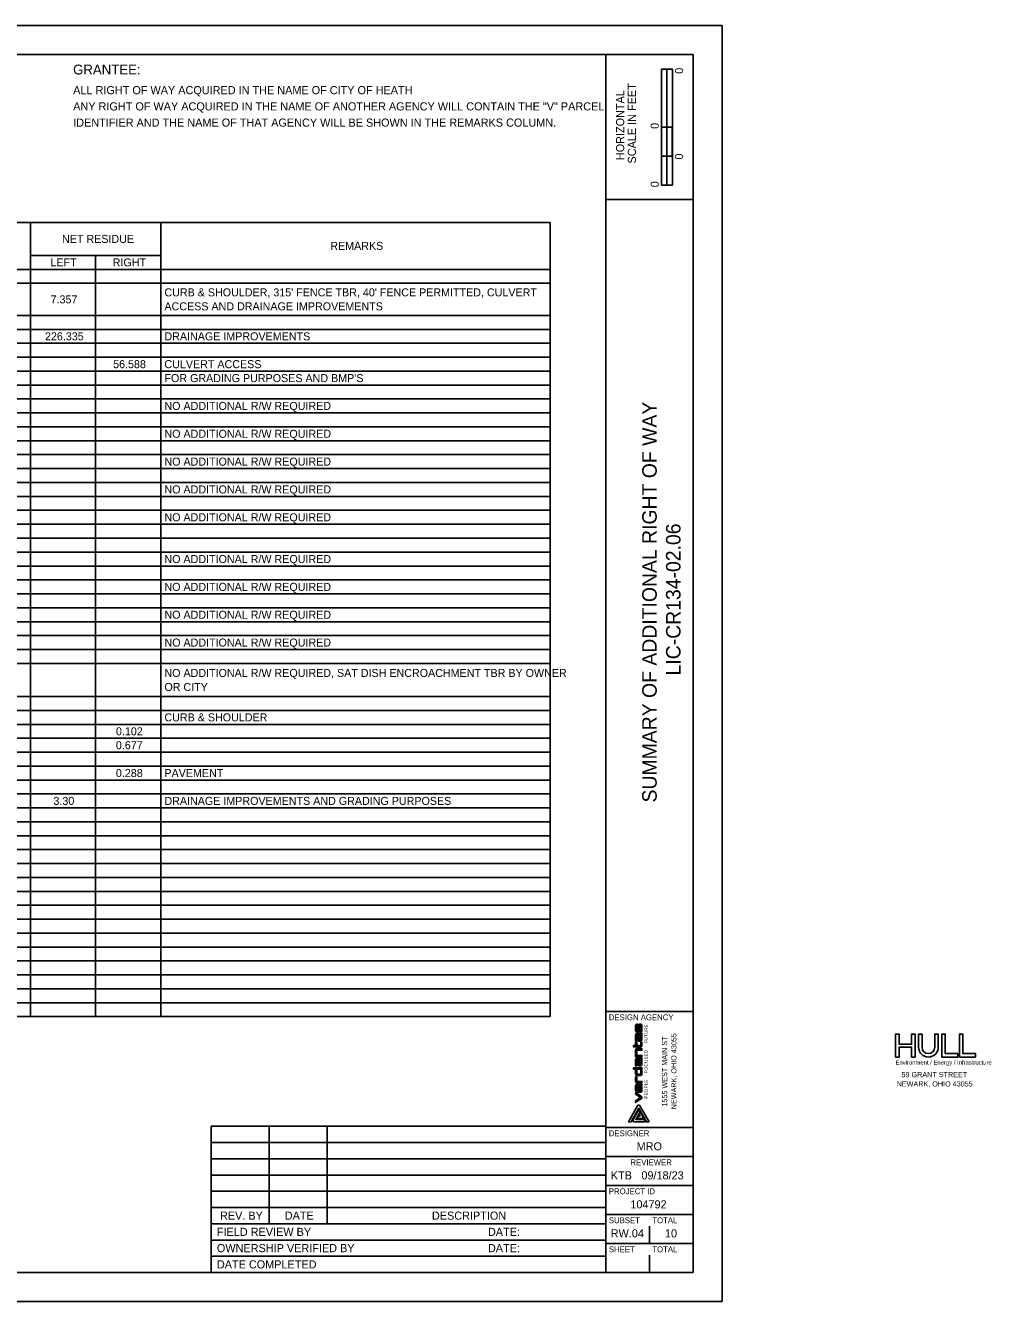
# Model space of a CAD drawing. Extents: x 0 to 38.6, y 0 to 22.
# Drawn here: x 22 to 38.59, y 0 to 22 of the extents above; entities that cross this region are included whole.
import ezdxf

# ---------------------------------------------------------------- set-up
doc = ezdxf.new("R2010")
doc.units = 0
for name, color, linetype in [('CS-ANNO-TTLB-LOGO', 7, 'Continuous'), ('Default', 7, 'Continuous'), ('SH_Border', 7, 'Continuous'), ('SH_Cut_Line', 7, 'Continuous'), ('SH_Data', 7, 'Continuous'), ('SH_Text', 7, 'Continuous')]:
    doc.layers.add(name, color=color, linetype=linetype)

msp = doc.modelspace()

# ---------------------------------------------------------------- linework, layer by layer
at = {"layer": 'CS-ANNO-TTLB-LOGO'}
for p, q in [((32.512, 4.761), (32.512, 4.668)), ((32.543, 4.783), (32.535, 4.783)), ((32.535, 4.645), (32.551, 4.645)), ((32.596, 4.783), (32.58, 4.783)), ((32.619, 4.668), (32.619, 4.761)), ((32.512, 4.488), (32.512, 4.6)), ((32.512, 4.063), (32.512, 4.175)), ((32.535, 3.894), (32.596, 3.894)), ((32.619, 3.633), (32.619, 3.745)), ((32.512, 3.723), (32.512, 3.633)), ((32.535, 3.61), (32.596, 3.61))]:
    msp.add_line(p, q, dxfattribs=at)
for points in [[(32.557, 4.761), (32.557, 4.673), (32.532, 4.673), (32.532, 4.761), (32.543, 4.761), (32.543, 4.783)], [(32.535, 4.623), (32.619, 4.623), (32.619, 4.51)], [(32.574, 4.668), (32.574, 4.761), (32.599, 4.761), (32.599, 4.673), (32.591, 4.673), (32.591, 4.645), (32.596, 4.645)], [(32.477, 4.412), (32.512, 4.412), (32.512, 4.468), (32.532, 4.468), (32.532, 4.412), (32.599, 4.412), (32.599, 4.468), (32.619, 4.468), (32.619, 4.412)], [(32.596, 4.389), (32.477, 4.389), (32.477, 4.412)], [(32.596, 4.488), (32.557, 4.488), (32.557, 4.6), (32.532, 4.6), (32.532, 4.488), (32.512, 4.488)], [(32.512, 4.339), (32.512, 4.22), (32.619, 4.22), (32.619, 4.243), (32.532, 4.243), (32.532, 4.333), (32.619, 4.333)], [(32.619, 4.333), (32.619, 4.361), (32.535, 4.361)], [(32.535, 4.198), (32.619, 4.198), (32.619, 4.085)], [(32.477, 4.029), (32.477, 4.007), (32.512, 4.007), (32.512, 3.917)], [(32.619, 3.917), (32.619, 4.029), (32.477, 4.029)], [(32.596, 4.063), (32.557, 4.063), (32.557, 4.175), (32.532, 4.175), (32.532, 4.063), (32.512, 4.063)], [(32.619, 3.793), (32.532, 3.793), (32.532, 3.872), (32.512, 3.872), (32.512, 3.793)], [(32.535, 3.77), (32.619, 3.77), (32.619, 3.793)], [(32.619, 3.745), (32.599, 3.745), (32.599, 3.633), (32.574, 3.633), (32.574, 3.745), (32.535, 3.745)]]:
    msp.add_lwpolyline(points, dxfattribs=at)
for points in [[(32.574, 4.6), (32.599, 4.6), (32.599, 4.51), (32.574, 4.51)], [(32.532, 4.007), (32.532, 3.917), (32.599, 3.917), (32.599, 4.007)], [(32.574, 4.175), (32.599, 4.175), (32.599, 4.085), (32.574, 4.085)], [(32.597, 3.516), (32.512, 3.457), (32.512, 3.43), (32.619, 3.505), (32.619, 3.528), (32.513, 3.603), (32.512, 3.575)], [(32.557, 3.723), (32.532, 3.723), (32.532, 3.633), (32.557, 3.633)]]:
    msp.add_lwpolyline(points, close=True, dxfattribs=at)
for centre, start, end in [((32.535, 4.761), 90, 180), ((32.535, 4.668), 180, 270), ((32.535, 4.6), 90, 180), ((32.551, 4.668), 270, 0), ((32.58, 4.761), 90, 180), ((32.596, 4.761), 360, 90), ((32.596, 4.668), 270, 0), ((32.596, 4.51), 270, 360), ((32.596, 4.412), 270, 360), ((32.535, 4.339), 90, 180), ((32.535, 4.175), 90, 180), ((32.596, 4.085), 270, 360), ((32.535, 3.917), 180, 270), ((32.535, 3.793), 180, 270), ((32.535, 3.723), 90, 180), ((32.596, 3.917), 270, 0), ((32.535, 3.633), 180, 270), ((32.596, 3.633), 270, 0)]:
    msp.add_arc(centre, 0.0225, start, end, dxfattribs=at)
at = {"layer": 'Default'}
for p, q in [((32.512, 4.761), (32.512, 4.668)), ((32.535, 4.645), (32.551, 4.645)), ((32.596, 4.783), (32.58, 4.783)), ((32.619, 4.668), (32.619, 4.761)), ((37.556, 4.275), (37.556, 4.275)), ((37.556, 4.275), (37.556, 4.275)), ((37.556, 4.215), (37.556, 4.215)), ((32.535, 3.894), (32.596, 3.894)), ((32.512, 3.723), (32.512, 3.633)), ((32.535, 3.61), (32.596, 3.61)), ((32.462, 3.126), (32.565, 3.309)), ((32.565, 3.309), (32.588, 3.269)), ((32.477, 3.098), (32.462, 3.126)), ((32.684, 3.098), (32.477, 3.098)), ((32.588, 3.269), (32.513, 3.138)), ((32.513, 3.138), (32.662, 3.138)), ((32.662, 3.138), (32.684, 3.098))]:
    msp.add_line(p, q, dxfattribs=at)
for points in [[(32.557, 4.761), (32.557, 4.673), (32.532, 4.673), (32.532, 4.761), (32.543, 4.761), (32.543, 4.783), (32.535, 4.783)], [(32.619, 4.51), (32.619, 4.623), (32.535, 4.623)], [(32.574, 4.668), (32.574, 4.761), (32.599, 4.761), (32.599, 4.673), (32.591, 4.673), (32.591, 4.645), (32.596, 4.645)], [(32.619, 4.412), (32.619, 4.468), (32.599, 4.468), (32.599, 4.412), (32.532, 4.412), (32.532, 4.468), (32.512, 4.468), (32.512, 4.412), (32.477, 4.412), (32.477, 4.389), (32.596, 4.389)], [(32.512, 4.6), (32.512, 4.488), (32.532, 4.488), (32.532, 4.6), (32.557, 4.6), (32.557, 4.488), (32.596, 4.488)], [(37.327, 4.611), (37.327, 4.611), (37.327, 4.215), (37.266, 4.215), (37.266, 4.383), (37.051, 4.383), (37.051, 4.215), (36.991, 4.215), (36.991, 4.611), (37.051, 4.611), (37.051, 4.436), (37.266, 4.436), (37.266, 4.611), (37.327, 4.611)], [(37.447, 4.383), (37.447, 4.611), (37.387, 4.611), (37.387, 4.383)], [(37.387, 4.383), (37.387, 4.611), (37.447, 4.611), (37.447, 4.383)], [(37.725, 4.383), (37.725, 4.611), (37.664, 4.611), (37.664, 4.383)], [(37.664, 4.383), (37.664, 4.611), (37.725, 4.611), (37.725, 4.383)], [(32.512, 4.339), (32.512, 4.22), (32.619, 4.22), (32.619, 4.243), (32.532, 4.243), (32.532, 4.333), (32.619, 4.333), (32.619, 4.361), (32.535, 4.361)], [(32.619, 4.085), (32.619, 4.198), (32.535, 4.198)], [(32.619, 3.917), (32.619, 4.029), (32.477, 4.029), (32.477, 4.007), (32.512, 4.007), (32.512, 3.917)], [(32.512, 4.175), (32.512, 4.063), (32.532, 4.063), (32.532, 4.175), (32.557, 4.175), (32.557, 4.063), (32.596, 4.063)], [(32.535, 3.77), (32.619, 3.77), (32.619, 3.793), (32.532, 3.793), (32.532, 3.872), (32.512, 3.872), (32.512, 3.793)], [(32.619, 3.633), (32.619, 3.745), (32.599, 3.745), (32.599, 3.633), (32.574, 3.633), (32.574, 3.745), (32.535, 3.745)]]:
    msp.add_lwpolyline(points, dxfattribs=at)
for points in [[(32.599, 4.6), (32.599, 4.51), (32.574, 4.51), (32.574, 4.6)], [(37.327, 4.611), (37.266, 4.611), (37.266, 4.436), (37.051, 4.436), (37.051, 4.611), (36.991, 4.611), (36.991, 4.215), (37.051, 4.215), (37.051, 4.383), (37.266, 4.383), (37.266, 4.215), (37.327, 4.215)], [(37.845, 4.611), (37.785, 4.611), (37.785, 4.215), (38.061, 4.215), (38.061, 4.275), (37.845, 4.275)], [(37.785, 4.611), (37.785, 4.215), (38.061, 4.215), (38.061, 4.275), (37.845, 4.275), (37.845, 4.611)], [(38.15, 4.611), (38.09, 4.611), (38.09, 4.215), (38.366, 4.215), (38.366, 4.275), (38.15, 4.275)], [(38.09, 4.611), (38.09, 4.215), (38.366, 4.215), (38.366, 4.275), (38.15, 4.275), (38.15, 4.611)], [(32.532, 4.007), (32.599, 4.007), (32.599, 3.917), (32.532, 3.917)], [(32.599, 4.175), (32.599, 4.085), (32.574, 4.085), (32.574, 4.175)], [(32.512, 3.457), (32.512, 3.43), (32.619, 3.505), (32.619, 3.528), (32.513, 3.603), (32.512, 3.575), (32.597, 3.516)], [(32.557, 3.723), (32.557, 3.633), (32.532, 3.633), (32.532, 3.723)], [(32.565, 3.332), (32.697, 3.098), (32.742, 3.098), (32.581, 3.384), (32.549, 3.384), (32.388, 3.098), (32.433, 3.098)], [(32.433, 3.098), (32.565, 3.332), (32.697, 3.098), (32.742, 3.098), (32.581, 3.384), (32.549, 3.384), (32.388, 3.098)], [(32.462, 3.126), (32.477, 3.098), (32.684, 3.098), (32.662, 3.138), (32.513, 3.138), (32.588, 3.269), (32.565, 3.309)], [(32.558, 3.194), (32.536, 3.155), (32.626, 3.155), (32.639, 3.178), (32.594, 3.258), (32.571, 3.218), (32.585, 3.194)], [(32.558, 3.194), (32.585, 3.194), (32.571, 3.218), (32.594, 3.258), (32.639, 3.178), (32.626, 3.155), (32.536, 3.155)]]:
    msp.add_lwpolyline(points, close=True, dxfattribs=at)
for centre, radius, start, end in [((32.535, 4.761), 0.0225, 90, 180), ((32.535, 4.668), 0.0225, 180, 270), ((32.535, 4.6), 0.0225, 90, 180), ((32.551, 4.668), 0.0225, 270, 0), ((32.58, 4.761), 0.0225, 90, 180), ((32.596, 4.761), 0.0225, 360, 90), ((32.596, 4.668), 0.0225, 270, 0), ((32.596, 4.51), 0.0225, 270, 0), ((32.596, 4.412), 0.0225, 270, 0), ((32.535, 4.339), 0.0225, 90, 180), ((32.535, 4.175), 0.0225, 90, 180), ((37.556, 4.383), 0.169, 180, 270.0443), ((37.556, 4.383), 0.169, 180, 270), ((37.556, 4.383), 0.108, 180, 270), ((37.556, 4.383), 0.108, 180, 270), ((37.556, 4.383), 0.108, 270, 0), ((37.556, 4.383), 0.169, 269.9557, 360), ((37.556, 4.383), 0.108, 270, 0), ((37.556, 4.383), 0.169, 270, 0), ((32.596, 4.085), 0.0225, 270, 0), ((32.535, 3.917), 0.0225, 180, 270), ((32.535, 3.793), 0.0225, 180, 270), ((32.535, 3.723), 0.0225, 90, 180), ((32.596, 3.917), 0.0225, 270, 0), ((32.535, 3.633), 0.0225, 180, 270), ((32.596, 3.633), 0.0225, 270, 0)]:
    msp.add_arc(centre, radius, start, end, dxfattribs=at)
at = {"layer": 'SH_Border'}
for p, q in [((32, 0.5), (32, 21.5)), ((32, 19), (33.5, 19)), ((32, 5), (33.5, 5)), ((32, 3), (33.5, 3)), ((32, 2.5), (33.5, 2.5)), ((32, 2), (33.5, 2)), ((32, 1.5), (33.5, 1.5)), ((32, 1), (33.5, 1))]:
    msp.add_line(p, q, dxfattribs=at)
msp.add_lwpolyline([(1.5, 21.5), (33.5, 21.5), (33.5, 0.5), (1.5, 0.5)], close=True, dxfattribs=at)
at = {"layer": 'SH_Cut_Line'}
msp.add_lwpolyline([(0, 0), (34, 0), (34, 22), (0, 22)], close=True, dxfattribs=at)
at = {"layer": 'SH_Data'}
for p, q in [((32.957, 19.25), (32.957, 21.25)), ((33.144, 21.25), (32.957, 21.25)), ((32.957, 20.25), (32.957, 21.25)), ((32.957, 21.25), (33.05, 21.25)), ((33.05, 21.25), (33.051, 21.25)), ((33.051, 21.25), (33.051, 20.25)), ((33.144, 21.25), (33.144, 19.25)), ((33.051, 20.25), (32.957, 20.25)), ((33.143, 20.25), (33.05, 20.25)), ((33.05, 20.25), (33.05, 19.75)), ((33.143, 19.75), (33.143, 20.25)), ((33.05, 19.75), (32.957, 19.75)), ((32.957, 19.75), (32.957, 19.25)), ((33.05, 19.75), (33.143, 19.75)), ((33.05, 19.25), (33.05, 19.75)), ((33.144, 19.25), (32.957, 19.25)), ((32.957, 19.25), (33.05, 19.25)), ((32.75, 4), (32.75, 4)), ((32.75, 1), (32.75, 1.3)), ((32.375, 0.675), (32.375, 0.675)), ((32.75, 0.5), (32.75, 0.8))]:
    msp.add_line(p, q, dxfattribs=at)
at = {"layer": 'SH_Text'}
for p, q in [((2.373, 18.606), (31.038, 18.606)), ((22.083, 18.606), (22.083, 4.911)), ((24.333, 18.606), (24.333, 4.911)), ((31.038, 18.606), (31.038, 4.911)), ((22.083, 18.036), (24.333, 18.036)), ((23.208, 18.036), (23.208, 4.911)), ((2.373, 17.796), (31.038, 17.796)), ((2.373, 17.556), (31.038, 17.556)), ((2.373, 17.001), (31.038, 17.001)), ((2.373, 16.761), (31.038, 16.761)), ((2.373, 16.521), (31.038, 16.521)), ((2.373, 16.281), (31.038, 16.281)), ((17.448, 16.041), (31.038, 16.041)), ((2.373, 15.801), (31.038, 15.801)), ((2.373, 15.561), (31.038, 15.561)), ((2.373, 15.321), (31.038, 15.321)), ((2.373, 15.081), (31.038, 15.081)), ((2.373, 14.841), (31.038, 14.841)), ((2.373, 14.601), (31.038, 14.601)), ((2.373, 14.361), (31.038, 14.361)), ((2.373, 14.121), (31.038, 14.121)), ((2.373, 13.881), (31.038, 13.881)), ((2.373, 13.641), (31.038, 13.641)), ((2.373, 13.401), (31.038, 13.401)), ((2.373, 13.161), (31.038, 13.161)), ((2.373, 12.921), (31.038, 12.921)), ((2.373, 12.681), (31.038, 12.681)), ((2.373, 12.441), (31.038, 12.441)), ((2.373, 12.201), (31.038, 12.201)), ((2.373, 11.961), (31.038, 11.961)), ((2.373, 11.721), (31.038, 11.721)), ((2.373, 11.481), (31.038, 11.481)), ((2.373, 11.241), (31.038, 11.241)), ((2.373, 11.001), (31.038, 11.001)), ((2.373, 10.431), (31.038, 10.431)), ((2.373, 10.191), (31.038, 10.191)), ((2.373, 9.951), (31.038, 9.951)), ((2.373, 9.711), (31.038, 9.711)), ((2.373, 9.471), (31.038, 9.471)), ((2.373, 9.231), (31.038, 9.231)), ((2.373, 8.991), (31.038, 8.991)), ((2.373, 8.751), (31.038, 8.751)), ((2.373, 8.511), (31.038, 8.511)), ((2.373, 8.271), (31.038, 8.271)), ((2.373, 8.031), (31.038, 8.031)), ((2.373, 7.791), (31.038, 7.791)), ((2.373, 7.551), (31.038, 7.551)), ((2.373, 7.311), (31.038, 7.311)), ((2.373, 7.071), (31.038, 7.071)), ((2.373, 6.831), (31.038, 6.831)), ((2.373, 6.591), (31.038, 6.591)), ((2.373, 6.351), (31.038, 6.351)), ((2.373, 6.111), (31.038, 6.111)), ((2.373, 5.871), (31.038, 5.871)), ((2.373, 5.631), (31.038, 5.631)), ((2.373, 5.391), (31.038, 5.391)), ((2.373, 5.151), (31.038, 5.151)), ((2.373, 4.911), (31.038, 4.911)), ((25.197, 3.02), (25.197, 0.5)), ((25.197, 3.02), (32, 3.02)), ((26.197, 3.02), (26.197, 1.34)), ((27.197, 3.02), (27.197, 1.34)), ((25.197, 2.74), (32, 2.74)), ((25.197, 2.46), (32, 2.46)), ((25.197, 2.18), (32, 2.18)), ((25.197, 1.9), (32, 1.9)), ((25.197, 1.62), (32, 1.62)), ((25.197, 1.34), (32, 1.34)), ((25.197, 1.06), (32, 1.06)), ((25.197, 0.78), (32, 0.78)), ((32, 0.5), (32, 0.5))]:
    msp.add_line(p, q, dxfattribs=at)

# ---------------------------------------------------------------- texts
at = {"layer": 'Default'}
for s, height, p in [('LIC-CR134-02.06', 0.25, (33.285, 10.794)), ('E', 0.0563, (32.72, 4.726)), ('R', 0.0563, (32.72, 4.67)), ('U', 0.0563, (32.72, 4.609)), ('T', 0.0563, (32.72, 4.56)), ('U', 0.0563, (32.72, 4.499)), ('F', 0.0563, (32.72, 4.448)), ('D', 0.0563, (32.72, 4.278)), ('E', 0.0563, (32.72, 4.225)), ('S', 0.0563, (32.72, 4.173)), ('U', 0.0563, (32.72, 4.114)), ('C', 0.0563, (32.72, 4.051)), ('O', 0.0563, (32.72, 3.98)), ('F', 0.0563, (32.72, 3.931)), ('E', 0.0563, (32.72, 3.773)), ('L', 0.0563, (32.72, 3.728)), ('P', 0.0563, (32.72, 3.675)), ('O', 0.0563, (32.72, 3.604)), ('E', 0.0563, (32.72, 3.551)), ('P', 0.0563, (32.72, 3.498))]:
    msp.add_text(s, height=height, rotation=90, dxfattribs=at).set_placement(p)
msp.add_text('Environment / Energy / Infrastructure ', height=0.07349, dxfattribs=at).set_placement((36.989, 4.085))
at = {"layer": 'SH_Data'}
for s, height, p in [('0', 0.14, (33.33, 21.168)), ('SCALE IN FEET', 0.14, (32.517, 19.621)), ('HORIZONTAL', 0.14, (32.315, 19.679)), ('0', 0.14, (32.91, 20.218)), ('0', 0.14, (33.33, 19.689)), ('0', 0.14, (32.91, 19.211)), ('SUMMARY OF ADDITIONAL RIGHT OF WAY', 0.25, (32.875, 8.604))]:
    msp.add_text(s, height=height, rotation=90, dxfattribs=at).set_placement(p)
for s, height, p in [('DESIGN AGENCY', 0.1, (32.05, 4.85)), ('DESIGNER', 0.1, (32.05, 2.85)), ('MRO', 0.14, (32.529, 2.605)), ('REVIEWER', 0.1, (32.422, 2.35)), ('KTB', 0.14, (32.084, 2.105)), ('09/18/23', 0.14, (32.611, 2.105)), ('PROJECT ID', 0.1, (32.05, 1.85)), ('104792', 0.14, (32.421, 1.605)), ('SUBSET', 0.1, (32.05, 1.35)), ('TOTAL', 0.1, (32.8, 1.35)), ('RW.04', 0.14, (32.082, 1.105)), ('10', 0.14, (33.017, 1.105)), ('SHEET', 0.1, (32.05, 0.85)), ('TOTAL', 0.1, (32.8, 0.85))]:
    msp.add_text(s, height=height, dxfattribs=at).set_placement(p)
at = {"layer": 'SH_Text'}
for s, height, p in [('GRANTEE:', 0.17, (22.82, 21.156)), ('ALL RIGHT OF WAY ACQUIRED IN THE NAME OF CITY OF HEATH', 0.14, (22.821, 20.816)), ('ANY RIGHT OF WAY ACQUIRED IN THE NAME OF ANOTHER AGENCY WILL CONTAIN THE "V" PARCEL', 0.14, (22.821, 20.536)), ('IDENTIFIER AND THE NAME OF THAT AGENCY WILL BE SHOWN IN THE REMARKS COLUMN.', 0.14, (22.821, 20.256)), ('NET RESIDUE', 0.138, (22.629, 18.252)), ('REMARKS', 0.138, (27.251, 18.132)), ('LEFT', 0.138, (22.43, 17.847)), ('RIGHT', 0.138, (23.502, 17.847)), ("CURB & SHOULDER, 315' FENCE TBR, 40' FENCE PERMITTED, CULVERT ", 0.138, (24.393, 17.33)), ('7.357', 0.138, (22.432, 17.209)), ('ACCESS AND DRAINAGE IMPROVEMENTS', 0.138, (24.393, 17.089)), ('226.335', 0.138, (22.335, 16.572)), ('DRAINAGE IMPROVEMENTS', 0.138, (24.393, 16.572)), ('56.588', 0.138, (23.509, 16.092)), ('CULVERT ACCESS', 0.138, (24.393, 16.092)), ("FOR GRADING PURPOSES AND BMP'S", 0.138, (24.393, 15.852)), ('NO ADDITIONAL R/W REQUIRED', 0.138, (24.393, 15.372)), ('NO ADDITIONAL R/W REQUIRED', 0.138, (24.393, 14.892)), ('NO ADDITIONAL R/W REQUIRED', 0.138, (24.393, 14.412)), ('NO ADDITIONAL R/W REQUIRED', 0.138, (24.393, 13.932)), ('NO ADDITIONAL R/W REQUIRED', 0.138, (24.393, 13.452)), ('NO ADDITIONAL R/W REQUIRED', 0.138, (24.393, 12.732)), ('NO ADDITIONAL R/W REQUIRED', 0.138, (24.393, 12.252)), ('NO ADDITIONAL R/W REQUIRED', 0.138, (24.393, 11.772)), ('NO ADDITIONAL R/W REQUIRED', 0.138, (24.393, 11.292)), ('NO ADDITIONAL R/W REQUIRED, SAT DISH ENCROACHMENT TBR BY OWNER ', 0.138, (24.393, 10.768)), ('OR CITY', 0.138, (24.393, 10.526)), ('CURB & SHOULDER', 0.138, (24.393, 10.002)), ('0.102', 0.138, (23.558, 9.762)), ('0.677', 0.138, (23.557, 9.522)), ('0.288', 0.138, (23.557, 9.042)), ('PAVEMENT', 0.138, (24.393, 9.042)), ('3.30', 0.138, (22.481, 8.562)), ('DRAINAGE IMPROVEMENTS AND GRADING PURPOSES', 0.138, (24.393, 8.562)), ('NEWARK, OHIO 43055', 0.09, (37.008, 3.707)), ('59 GRANT STREET', 0.09, (37.092, 3.867)), ('REV. BY', 0.14, (25.35, 1.41)), ('DATE', 0.14, (26.466, 1.41)), ('DESCRIPTION', 0.14, (29.002, 1.41)), ('FIELD REVIEW BY', 0.14, (25.297, 1.13)), ('DATE:', 0.14, (29.967, 1.13)), ('OWNERSHIP VERIFIED BY', 0.14, (25.297, 0.85)), ('DATE:', 0.14, (29.967, 0.85)), ('DATE COMPLETED', 0.14, (25.297, 0.57))]:
    msp.add_text(s, height=height, dxfattribs=at).set_placement(p)
for s, p in [('1555 WEST MAIN ST', (33.055, 3.36)), ('NEWARK, OHIO 43055', (33.215, 3.314))]:
    msp.add_text(s, height=0.09, rotation=90, dxfattribs=at).set_placement(p)

doc.saveas('drawing.dxf')
